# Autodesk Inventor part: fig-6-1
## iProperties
Created: 2004-05
Part Number: fig-6-1
Document SubType Name: Modeling
Designer: CADCIM Technologies
Manufacturer: Standard
Standards Organization: Custom
Author: CADCIM Technologies
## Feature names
1. Extrusion1
2. Hole1
3. Circular Pattern1
